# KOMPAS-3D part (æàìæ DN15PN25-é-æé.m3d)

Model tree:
1. Объединить компоненты:1  (labels: СЕНС DN15PN25-В)
2. Эскиз:1
3. Операция выдавливания:1
     Расстояние 1 = 14
4. Фаска:1
     Угол = 45; Длина 1 = 2; Длина 2 = 2

Referenced files in D:\Савин\!СЕНСОР\3D для заказчика\!Новый перечень\СЕНС\3. СЕНС-В\DN15\: СЕНС DN15PN25-В.a3d
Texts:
  СЕНС DN15PN25-В-СВ
  ООО НПП Сенсор
  СЕНС DN15PN25-В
